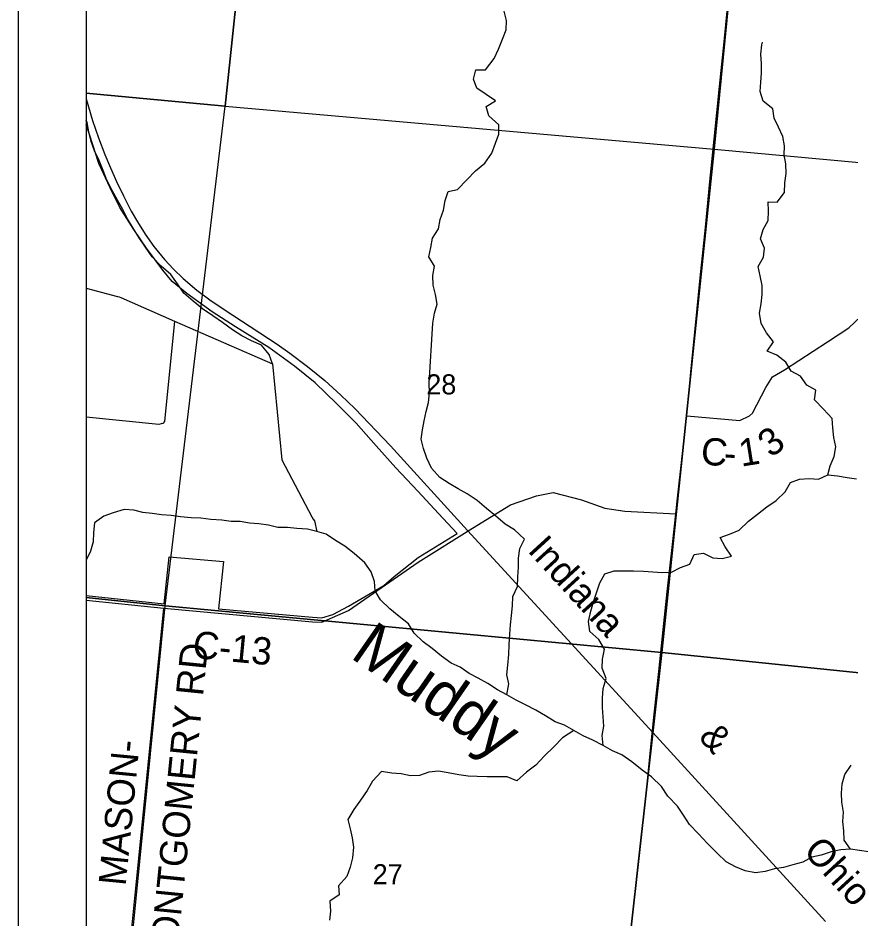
# Model space of a CAD drawing. Extents: x 0 to 34, y -4 to 22.
# Drawn here: x 2 to 3.221, y 19.263 to 20.584 of the extents above; entities that cross this region are included whole.
import ezdxf

# ---------------------------------------------------------------- set-up
doc = ezdxf.new("R2010")
doc.units = 0
for name, color, linetype in [('GM_X_Corporation', 7, 'Continuous'), ('GM_X_County_Road', 7, 'Continuous'), ('GM_X_County_Road_Text', 7, 'Continuous'), ('GM_X_Minor_River', 7, 'Continuous'), ('GM_X_Minor_River_Text', 7, 'Continuous'), ('GM_X_Rail_Line', 7, 'Continuous'), ('GM_X_Rail_Line_Text', 7, 'Continuous'), ('GM_X_Section', 7, 'Continuous'), ('GM_X_Section_Text', 7, 'Continuous'), ('GM_X_State_Route', 7, 'Continuous'), ('SH_Data', 7, 'Continuous'), ('SN_P_Text', 7, 'Continuous')]:
    doc.layers.add(name, color=color, linetype=linetype)

msp = doc.modelspace()

# ---------------------------------------------------------------- linework, layer by layer
at = {"layer": 'GM_X_Corporation'}
msp.add_lwpolyline([(2.1, 20.4273), (2.1, 19.7375), (2.2143, 19.7253), (2.2215, 19.7942), (2.3012, 19.7872), (2.2939, 19.7181), (2.4316, 19.7056), (2.4452, 19.7049), (2.4611, 19.7097), (2.4845, 19.7221), (2.5361, 19.7524), (2.551, 19.7656), (2.5862, 19.793), (2.6436, 19.8286), (2.6163, 19.8578), (2.5859, 19.8903), (2.5537, 19.9247), (2.5247, 19.9568), (2.4954, 19.99), (2.4665, 20.0191), (2.4356, 20.0491), (2.4053, 20.0739), (2.3675, 20.1011), (2.3185, 20.1313), (2.2843, 20.1533), (2.2473, 20.1802), (2.2259, 20.1977), (2.2123, 20.2144), (2.1885, 20.2468), (2.1698, 20.2741), (2.1492, 20.3064), (2.1348, 20.3349), (2.1184, 20.371), (2.1045, 20.4132)], close=True, dxfattribs=at)
at = {"layer": 'GM_X_County_Road'}
msp.add_line((2.1, 19.7308), (2.2136, 19.7187), dxfattribs=at)
for points in [[(2.98, 20.0008), (3.0576, 19.994), (3.0721, 20.0007), (3.0765, 20.0049), (3.0956, 20.0423), (3.1058, 20.0582), (3.123, 20.0685), (3.186, 20.1094), (3.2176, 20.13), (3.3513, 20.2563)], [(2.2136, 19.7187), (2.4316, 19.699), (2.4452, 19.6982), (2.4845, 19.7154), (2.5862, 19.7863), (2.6662, 19.836), (2.7218, 19.8703), (2.76, 19.8835), (2.7844, 19.8884), (2.8256, 19.8778), (2.8598, 19.8657), (2.8893, 19.8611), (2.964, 19.8572)], [(2.2084, 19.0131), (2.2083, 19.0142), (2.2053, 19.0377), (2.2051, 19.0384), (2.1953, 19.091), (2.194, 19.1038), (2.1953, 19.1169), (2.1923, 19.1357), (2.1833, 19.1517), (2.1571, 19.1528), (2.1585, 19.167), (2.2136, 19.7187)]]:
    msp.add_lwpolyline(points, dxfattribs=at)
at = {"layer": 'GM_X_Minor_River'}
for points in [[(2.7162, 19.5919), (2.7191, 19.608), (2.7162, 19.6214), (2.7178, 19.6353), (2.7194, 19.6508), (2.7199, 19.6655), (2.7205, 19.6808), (2.7218, 19.6945), (2.7229, 19.7084), (2.7247, 19.7223), (2.7253, 19.7362), (2.7319, 19.7507), (2.7325, 19.7649), (2.7333, 19.7788), (2.7336, 19.7924), (2.7352, 19.8066), (2.7421, 19.82), (2.7277, 19.8339), (2.7141, 19.8419), (2.6999, 19.8543), (2.6863, 19.8652), (2.6727, 19.877), (2.6583, 19.8867), (2.6449, 19.8939), (2.6316, 19.9019), (2.6182, 19.9105), (2.6057, 19.9244), (2.5993, 19.9386), (2.5942, 19.953), (2.591, 19.9667), (2.5926, 19.9803), (2.5953, 19.9937), (2.5982, 20.0071), (2.6017, 20.0205), (2.603, 20.0347), (2.6027, 20.0489), (2.6081, 20.1369), (2.6102, 20.1514), (2.6142, 20.1648), (2.6118, 20.1787), (2.6083, 20.1924), (2.6078, 20.2065), (2.6105, 20.2205), (2.6022, 20.2341), (2.6051, 20.2478), (2.6075, 20.2614), (2.6161, 20.2751), (2.6185, 20.2887), (2.6236, 20.3024), (2.626, 20.3163), (2.6305, 20.3297), (2.6439, 20.3329), (2.6575, 20.3466), (2.6705, 20.3599), (2.6839, 20.3715), (2.6943, 20.3859), (2.6996, 20.4004), (2.7047, 20.4138), (2.7045, 20.4274), (2.69, 20.4405), (2.686, 20.4542), (2.6999, 20.4627), (2.686, 20.4721), (2.6724, 20.481), (2.6676, 20.4946), (2.6708, 20.508), (2.6852, 20.5083), (2.6975, 20.5246), (2.7039, 20.5382), (2.7101, 20.553), (2.7151, 20.5669), (2.7157, 20.5806), (2.7122, 20.5939)], [(3.1869, 19.9145), (3.1901, 19.9278), (3.1962, 19.9412), (3.1984, 19.9554), (3.1957, 19.9693), (3.1941, 19.9833), (3.1928, 19.9972), (3.1802, 20.0108), (3.1671, 20.0245), (3.169, 20.0384), (3.1557, 20.0456), (3.1466, 20.059), (3.1332, 20.0662), (3.1252, 20.0796), (3.1119, 20.0898), (3.098, 20.0957), (3.1073, 20.1093), (3.0969, 20.1227), (3.0889, 20.1364), (3.0868, 20.1514), (3.0889, 20.165), (3.0903, 20.1787), (3.0903, 20.1921), (3.0876, 20.2062), (3.0846, 20.2199), (3.0924, 20.2333), (3.0937, 20.2469), (3.0881, 20.2603), (3.0921, 20.274), (3.0993, 20.2874), (3.0999, 20.301), (3.0991, 20.3144), (3.1124, 20.3141), (3.1234, 20.3281), (3.1239, 20.3425), (3.1255, 20.3562), (3.1252, 20.3701), (3.1226, 20.3835), (3.1234, 20.3969), (3.1207, 20.4102), (3.1145, 20.4239), (3.1079, 20.4373), (3.1063, 20.4507), (3.0921, 20.4622), (3.0876, 20.4764), (3.0884, 20.49), (3.0897, 20.5034), (3.0897, 20.5171), (3.0884, 20.531), (3.0902, 20.5449), (3.0908, 20.5484)], [(2.3729, 20.077), (2.3678, 20.0909), (2.3566, 20.1046), (2.3422, 20.111), (2.328, 20.118), (2.3141, 20.1268), (2.2994, 20.1375), (2.2856, 20.1474), (2.2701, 20.1576), (2.2565, 20.1688), (2.2431, 20.1809), (2.2338, 20.1943), (2.2239, 20.2079), (2.21, 20.2205), (2.1967, 20.2341), (2.1868, 20.2483), (2.1777, 20.262), (2.1689, 20.2762), (2.1606, 20.2896), (2.1537, 20.3035), (2.1457, 20.3171), (2.1379, 20.3311), (2.1302, 20.3463), (2.1248, 20.3605), (2.119, 20.375), (2.1123, 20.3892), (2.1072, 20.4031), (2.1037, 20.417), (2.1011, 20.4309), (2.1, 20.4343)], [(2.1, 20.1878), (2.1457, 20.1758), (2.1483, 20.1752), (2.1507, 20.1742), (2.2293, 20.1398)], [(2.2293, 20.1398), (2.2148, 19.9924), (2.2124, 19.9895), (2.2097, 19.9892), (2.2063, 19.9884), (2.1, 19.9991)], [(2.2293, 20.1398), (2.3729, 20.077), (2.3865, 19.9362), (2.4305, 19.8527), (2.4324, 19.8492), (2.4343, 19.8468), (2.4377, 19.8315)], [(2.8577, 19.5178), (2.8558, 19.5322), (2.8585, 19.5462), (2.8577, 19.5598), (2.8566, 19.5735), (2.8564, 19.5871), (2.8574, 19.6013), (2.862, 19.616), (2.8558, 19.631), (2.8566, 19.6444), (2.8596, 19.6586), (2.851, 19.6728), (2.8377, 19.6848), (2.8361, 19.6993), (2.8393, 19.7145), (2.8435, 19.7282), (2.8476, 19.7416), (2.8526, 19.756), (2.8601, 19.7694), (2.8737, 19.7739), (2.9018, 19.7739), (2.9167, 19.7734), (2.9301, 19.7723), (2.9439, 19.771), (2.9576, 19.7718), (2.9709, 19.7785), (2.9845, 19.7836), (2.9907, 19.7975), (3.0043, 19.7996), (3.0182, 19.7929), (3.032, 19.7916), (3.0457, 19.7954), (3.0363, 19.809), (3.0291, 19.8224), (3.0427, 19.8272), (3.0566, 19.8331), (3.0702, 19.8467), (3.0838, 19.8569), (3.0975, 19.8674), (3.1108, 19.8767), (3.1244, 19.8893), (3.1319, 19.903), (3.1452, 19.908), (3.1591, 19.9091), (3.173, 19.908), (3.1869, 19.9145), (3.201, 19.9129), (3.2152, 19.9104), (3.2285, 19.9083)], [(2.9663, 19.4289), (2.9522, 19.4434), (2.9428, 19.4573), (2.9284, 19.4715), (2.9146, 19.4817), (2.8996, 19.4937), (2.8847, 19.5039), (2.871, 19.5098), (2.8577, 19.5178), (2.8425, 19.5253), (2.8281, 19.532), (2.8144, 19.5397), (2.8008, 19.5472), (2.7872, 19.5521), (2.7731, 19.5609), (2.7586, 19.5692), (2.7445, 19.5767), (2.7301, 19.5842), (2.7162, 19.5919), (2.7026, 19.5992), (2.6887, 19.6085), (2.6745, 19.6163), (2.6612, 19.623), (2.6478, 19.6326), (2.6345, 19.6385), (2.6206, 19.6487), (2.607, 19.6597), (2.5936, 19.6698), (2.5803, 19.6822), (2.5723, 19.6958), (2.5587, 19.7068), (2.5448, 19.718), (2.5312, 19.7311), (2.5234, 19.7445), (2.5226, 19.7579), (2.5173, 19.7721), (2.508, 19.7855), (2.4927, 19.7991), (2.4789, 19.8096), (2.465, 19.8181), (2.4516, 19.8272), (2.4377, 19.8315), (2.4241, 19.8347), (2.4084, 19.8355), (2.3948, 19.8371), (2.3806, 19.8371), (2.367, 19.8404), (2.3528, 19.8425), (2.339, 19.8436), (2.3256, 19.846), (2.3123, 19.846), (2.2986, 19.8479), (2.2826, 19.8487), (2.2679, 19.8508), (2.2535, 19.8516), (2.238, 19.8529), (2.2244, 19.8546), (2.2103, 19.8556), (2.1964, 19.8578), (2.183, 19.8591), (2.1697, 19.8628), (2.1553, 19.8637), (2.1395, 19.8588), (2.1256, 19.8538), (2.1123, 19.8438), (2.1104, 19.8299), (2.1099, 19.8163), (2.1062, 19.8024), (2.1, 19.7895)], [(2.8144, 19.5397), (2.7979, 19.529), (2.7851, 19.5157), (2.7717, 19.5023), (2.7589, 19.4889), (2.745, 19.4785), (2.7309, 19.4659), (2.717, 19.4715), (2.7023, 19.4715), (2.6876, 19.4718), (2.6729, 19.4723), (2.6596, 19.4726), (2.646, 19.4744), (2.6302, 19.4777), (2.6163, 19.4801), (2.6022, 19.4787), (2.5883, 19.4736), (2.5749, 19.4731), (2.5613, 19.4763), (2.5477, 19.4769), (2.5325, 19.4793), (2.5194, 19.4653), (2.5114, 19.4517), (2.5021, 19.4375), (2.4919, 19.4236), (2.4834, 19.4091), (2.4866, 19.3955), (2.4895, 19.3821), (2.4914, 19.3685), (2.49, 19.3529), (2.4866, 19.3395), (2.4818, 19.3254), (2.4695, 19.312), (2.4705, 19.2986), (2.4567, 19.2895), (2.4577, 19.275), (2.4564, 19.2617)], [(3.2197, 19.3655), (3.2106, 19.3789), (3.2101, 19.3925), (3.2085, 19.4064), (3.2096, 19.4201), (3.2072, 19.4345), (3.2069, 19.4479), (3.2077, 19.4613), (3.2117, 19.4752), (3.2208, 19.4886)], [(3.2464, 19.3617), (3.2197, 19.3655), (3.2056, 19.3649), (3.1917, 19.362), (3.177, 19.3567), (3.1634, 19.3537), (3.15, 19.3467), (3.1356, 19.3425), (3.1217, 19.339), (3.1084, 19.3368), (3.0948, 19.3331), (3.0806, 19.3312), (3.0657, 19.3339), (3.0515, 19.3398), (3.0379, 19.347), (3.0243, 19.3599), (3.0101, 19.3746), (2.997, 19.388), (2.9842, 19.4019), (2.9754, 19.4153), (2.9663, 19.4289)]]:
    msp.add_lwpolyline(points, dxfattribs=at)
at = {"layer": 'GM_X_Rail_Line'}
msp.add_lwpolyline([(2.1, 20.4655), (2.1, 20.4655), (2.1093, 20.4337), (2.1178, 20.4086), (2.1273, 20.3838), (2.1354, 20.3645), (2.1444, 20.3443), (2.1545, 20.3233), (2.1658, 20.301), (2.1751, 20.2851), (2.1861, 20.2674), (2.199, 20.2492), (2.2147, 20.2301), (2.2276, 20.216), (2.2419, 20.2022), (2.2622, 20.1849), (2.2813, 20.1707), (2.2975, 20.1595), (2.3146, 20.1485), (2.3798, 20.106), (2.3983, 20.0928), (2.4243, 20.0734), (2.4496, 20.0526), (2.4732, 20.0314), (2.4938, 20.0116), (2.5458, 19.9569), (2.6585, 19.8326), (2.9301, 19.5367), (3.1834, 19.2594)], dxfattribs=at)
at = {"layer": 'GM_X_Section'}
for points in [[(2.3502, 20.9), (2.1, 20.9), (2.1, 20.4741), (2.3034, 20.4548)], [(3.0701, 20.9), (2.3502, 20.9), (2.3034, 20.4548), (3.0199, 20.3919)], [(3.7736, 20.9), (3.0701, 20.9), (3.0199, 20.3919), (3.7177, 20.3277)], [(2.1, 20.4741), (2.1, 19.7347), (2.2154, 19.7225), (2.3034, 20.4548)], [(2.3034, 20.4548), (3.0199, 20.3919), (2.9432, 19.6541), (2.2154, 19.7225)], [(3.0199, 20.3919), (3.7177, 20.3277), (3.6409, 19.5822), (2.9432, 19.6541)], [(2.1, 19.7347), (2.1, 19.0266), (2.1461, 19.0221), (2.2154, 19.7225)], [(2.2154, 19.7225), (2.9432, 19.6541), (2.8648, 18.9493), (2.1461, 19.0221)], [(2.9432, 19.6541), (3.6409, 19.5822), (3.5731, 18.8738), (2.8648, 18.9493)]]:
    msp.add_lwpolyline(points, close=True, dxfattribs=at)
at = {"layer": 'GM_X_State_Route'}
for points in [[(2.9655, 19.8709), (2.9656, 19.8713), (2.974, 19.9502), (2.98, 20.0008), (2.9863, 20.0705), (2.9929, 20.1334), (2.9997, 20.2031), (3.0072, 20.2769), (3.014, 20.3444), (3.0203, 20.4066), (3.0279, 20.4837), (3.0346, 20.5491), (3.0417, 20.6195), (3.047, 20.6825), (3.0498, 20.7062), (3.0525, 20.7247), (3.0531, 20.7295)], [(2.8654, 18.9574), (2.8703, 19.0001), (2.8775, 19.0636), (2.8843, 19.1233), (2.8926, 19.1972), (2.9005, 19.2667), (2.907, 19.3262), (2.9136, 19.3875), (2.9208, 19.4513), (2.9264, 19.5057), (2.9323, 19.5635), (2.9392, 19.6262), (2.9455, 19.687), (2.9514, 19.7427), (2.959, 19.8121), (2.964, 19.8572), (2.9655, 19.8709)]]:
    msp.add_lwpolyline(points, dxfattribs=at)
at = {"layer": 'SH_Data'}
for p, q in [((2, 21), (2, 14)), ((2.1, 20.9), (2.1, 14.1))]:
    msp.add_line(p, q, dxfattribs=at)
at = {"layer": 'SN_P_Text'}
msp.add_lwpolyline([(8.9, 14.1), (8.9, 20.9), (2.1, 20.9), (2.1, 14.1)], close=True, dxfattribs=at)

# ---------------------------------------------------------------- texts
at = {"layer": 'GM_X_County_Road_Text'}
for s, rotation, p in [('3', 37.05, (3.1034, 19.9385)), ('C', 354.308, (2.9993, 19.9302)), ('1', 9.1455, (3.0597, 19.9263)), ('-', 356.4951, (3.0337, 19.9268)), ('C-13', 354.4948, (2.2547, 19.6462)), ('MONTGOMERY RD', 84.2816, (2.2302, 19.1811)), ('MASON-', 84.4107, (2.1577, 19.311))]:
    msp.add_text(s, height=0.04, rotation=rotation, dxfattribs=at).set_placement(p)
at = {"layer": 'GM_X_Minor_River_Text'}
msp.add_text('Muddy', height=0.06666, rotation=325.3113, dxfattribs=at).set_placement((2.4851, 19.6474))
at = {"layer": 'GM_X_Rail_Line_Text'}
for s, height, rotation, p in [('Indiana', 0.03975, 312.4471, (2.7455, 19.8027)), ('&', 0.0398, 312.1842, (2.996, 19.529)), ('Ohio', 0.03975, 312.6325, (3.1493, 19.3614))]:
    msp.add_text(s, height=height, rotation=rotation, dxfattribs=at).set_placement(p)
at = {"layer": 'GM_X_Section_Text'}
for s, p in [('28', (2.5984, 20.0323)), ('27', (2.5198, 19.3142))]:
    msp.add_text(s, height=0.02944, rotation=0, dxfattribs=at).set_placement(p)

doc.saveas('drawing.dxf')
